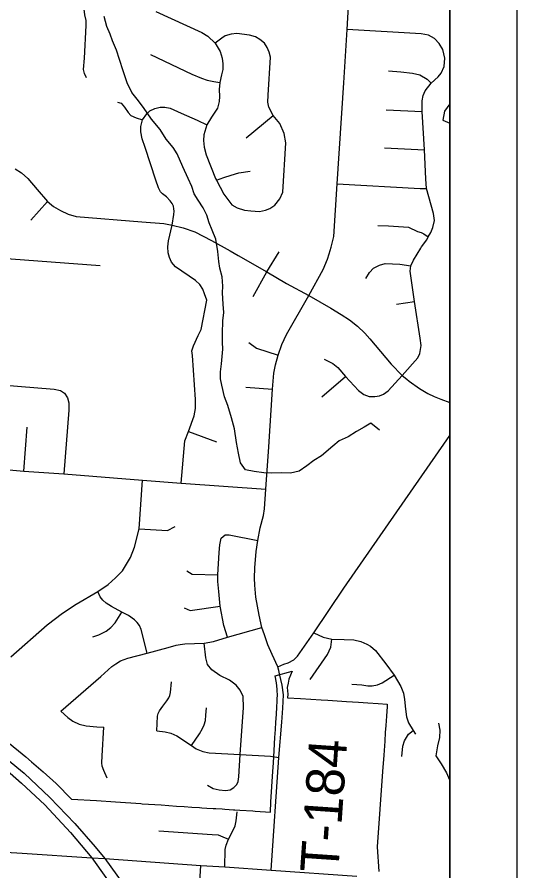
# Model space of a CAD drawing. Extents: x 0 to 34, y 0 to 22.
# Drawn here: x 28.267 to 29.011, y 5.753 to 7.023 of the extents above; entities that cross this region are included whole.
import ezdxf

# ---------------------------------------------------------------- set-up
doc = ezdxf.new("R2010")
doc.units = 0
for name, color, linetype in [('GM_X_City_Street', 7, 'Continuous'), ('GM_X_Corporation', 7, 'Continuous'), ('GM_X_County_Road', 7, 'Continuous'), ('GM_X_Interstate_Route', 7, 'Continuous'), ('GM_X_Minor_River', 7, 'Continuous'), ('GM_X_Township_Road', 7, 'Continuous'), ('GM_X_Township_Road_Text', 7, 'Continuous'), ('SH_Data', 7, 'Continuous')]:
    doc.layers.add(name, color=color, linetype=linetype)

msp = doc.modelspace()

# ---------------------------------------------------------------- linework, layer by layer
at = {"layer": 'GM_X_City_Street'}
for p, q in [((28.6081, 6.8439), (28.6479, 6.8769)), ((28.8166, 6.8855), (28.8699, 6.8828)), ((28.8141, 6.8288), (28.8733, 6.8258)), ((28.2873, 6.7211), (28.312, 6.7488)), ((28.6387, 6.6443), (28.6569, 6.6739)), ((28.6182, 6.6075), (28.6387, 6.6443)), ((28.8318, 6.5961), (28.8588, 6.6001)), ((28.7205, 6.4584), (28.7556, 6.4884)), ((28.84, 6.4902), (28.8471, 6.4846)), ((28.6074, 6.4726), (28.6472, 6.4697)), ((28.277, 6.3475), (28.2821, 6.4134)), ((28.5219, 6.4067), (28.5638, 6.3911))]:
    msp.add_line(p, q, dxfattribs=at)
for points in [[(28.3703, 6.933), (28.3674, 6.9396), (28.3655, 6.9453), (28.367, 6.9622), (28.3698, 7.0108), (28.3698, 7.0185), (28.3677, 7.027), (28.3665, 7.0352), (28.3679, 7.0488)], [(28.4733, 7.0319), (28.5417, 7.0004), (28.5508, 6.9952), (28.5617, 6.9846), (28.5692, 6.9721), (28.5723, 6.9622), (28.5734, 6.9537), (28.5734, 6.9456), (28.5714, 6.9375), (28.5685, 6.9263), (28.5679, 6.9159), (28.5681, 6.9052), (28.5679, 6.8977), (28.5654, 6.888), (28.5564, 6.8744), (28.5494, 6.863), (28.545, 6.8483), (28.5442, 6.84), (28.5452, 6.8297), (28.5483, 6.8185), (28.5623, 6.783), (28.5636, 6.7806), (28.5745, 6.7601), (28.5868, 6.744), (28.5947, 6.7394), (28.6053, 6.7359), (28.615, 6.735), (28.6277, 6.7342), (28.6366, 6.7359), (28.6432, 6.7386), (28.6508, 6.7437)], [(28.6373, 6.3207), (28.6417, 6.3841), (28.6472, 6.4697), (28.6491, 6.4936), (28.6514, 6.5057), (28.6557, 6.5205), (28.6611, 6.5362), (28.668, 6.551), (28.7011, 6.6092), (28.7224, 6.6478), (28.7291, 6.6631), (28.7315, 6.6709), (28.7345, 6.6811), (28.7386, 6.6971), (28.7436, 6.7755), (28.7532, 6.9254), (28.7582, 7.0052), (28.7603, 7.0396)], [(28.879, 6.6963), (28.8829, 6.7031), (28.886, 6.7103), (28.8884, 6.7205), (28.8866, 6.7311), (28.8763, 6.7682), (28.8753, 6.7828), (28.8733, 6.8258), (28.8699, 6.8828), (28.8699, 6.8987), (28.8717, 6.9069), (28.8744, 6.9136), (28.8836, 6.9249), (28.8936, 6.9343), (28.8984, 6.94), (28.9027, 6.95), (28.9038, 6.9623), (28.9006, 6.9751), (28.8954, 6.9842), (28.8883, 6.9917), (28.8795, 6.9963), (28.8683, 6.9983), (28.7582, 7.0052)], [(28.6508, 6.7437), (28.6582, 6.7529), (28.6623, 6.7627), (28.6668, 6.8365), (28.6643, 6.8502), (28.6582, 6.8652), (28.6479, 6.8769), (28.6419, 6.8894), (28.6404, 6.8969), (28.6406, 6.9074), (28.644, 6.964), (28.6423, 6.9713), (28.6394, 6.9783), (28.6353, 6.9847), (28.6285, 6.9903), (28.6217, 6.9939), (28.6131, 6.9967), (28.5942, 6.9989), (28.5854, 6.9982), (28.5769, 6.9956), (28.5716, 6.9923), (28.5617, 6.9846)], [(28.4653, 6.968), (28.5272, 6.9386), (28.5413, 6.9324), (28.5497, 6.9296), (28.5598, 6.9276), (28.5685, 6.9263)], [(28.8197, 6.9434), (28.838, 6.9418), (28.8555, 6.9402), (28.8665, 6.9377), (28.8774, 6.9311), (28.8836, 6.9249)], [(28.4166, 6.8966), (28.4216, 6.8953), (28.4267, 6.8894), (28.4322, 6.8815), (28.4364, 6.8769), (28.4441, 6.8734), (28.4535, 6.8703)], [(28.4977, 6.7137), (28.5002, 6.7295), (28.5009, 6.7348), (28.5003, 6.7383), (28.4998, 6.7421), (28.4978, 6.746), (28.4947, 6.75), (28.4891, 6.7559), (28.4836, 6.7605), (28.4805, 6.7632), (28.4774, 6.7691), (28.4735, 6.7809), (28.4574, 6.8294), (28.4533, 6.8424), (28.4511, 6.8529), (28.4511, 6.8606), (28.4535, 6.8703), (28.4599, 6.8797), (28.4647, 6.8839), (28.4721, 6.8876), (28.48, 6.8894), (28.4869, 6.8894), (28.495, 6.8878), (28.511, 6.8806), (28.5352, 6.8701), (28.5494, 6.863)], [(28.264, 6.7976), (28.2735, 6.7917), (28.283, 6.7832), (28.2966, 6.7669), (28.312, 6.7488), (28.3211, 6.7416), (28.3315, 6.7354), (28.3431, 6.7301), (28.3549, 6.7266), (28.4524, 6.7187), (28.4854, 6.7164), (28.4977, 6.7137), (28.5142, 6.7098), (28.5317, 6.7037), (28.5565, 6.691), (28.584, 6.6754), (28.596, 6.6686)], [(28.5636, 6.7806), (28.5748, 6.7848), (28.5858, 6.7884), (28.5972, 6.7917), (28.6139, 6.7941)], [(28.7436, 6.7755), (28.8671, 6.7684), (28.8763, 6.7682)], [(28.5114, 6.3296), (28.5166, 6.3929), (28.5219, 6.4067), (28.5304, 6.4302), (28.5326, 6.4409), (28.5327, 6.4542), (28.5278, 6.5196), (28.5271, 6.5267), (28.5294, 6.5344), (28.5367, 6.5494), (28.5408, 6.5585), (28.5493, 6.6021), (28.5461, 6.6115), (28.5433, 6.6187), (28.5387, 6.6255), (28.5323, 6.6314), (28.5025, 6.6517), (28.497, 6.6589), (28.4937, 6.6656), (28.4918, 6.6728), (28.4915, 6.6813), (28.4924, 6.6904), (28.4977, 6.7137)], [(28.804, 6.7132), (28.8197, 6.7126), (28.8496, 6.711), (28.8632, 6.7045), (28.8685, 6.7029), (28.8726, 6.701), (28.879, 6.6963)], [(28.84, 6.4902), (28.8635, 6.5164), (28.8664, 6.5227), (28.8683, 6.5348), (28.8669, 6.5457), (28.8588, 6.6001), (28.8523, 6.6453), (28.8532, 6.6531), (28.8569, 6.6617), (28.868, 6.6795), (28.869, 6.6813), (28.8767, 6.6918), (28.879, 6.6963)], [(28.0413, 6.6621), (28.0579, 6.6738), (28.0641, 6.6777), (28.0729, 6.6787), (28.0821, 6.6775), (28.1973, 6.6683), (28.2245, 6.6664), (28.3905, 6.654)], [(28.596, 6.6686), (28.6387, 6.6443), (28.6681, 6.627), (28.7011, 6.6092)], [(28.7859, 6.6346), (28.7914, 6.6435), (28.7977, 6.65), (28.8064, 6.6542), (28.815, 6.6565), (28.8366, 6.6556), (28.8532, 6.6531)], [(28.7011, 6.6092), (28.7341, 6.5902), (28.7495, 6.5809), (28.762, 6.5728), (28.7736, 6.5635), (28.7844, 6.5531), (28.7922, 6.5447), (28.8001, 6.5354), (28.8239, 6.5069), (28.84, 6.4902)], [(28.6117, 6.5394), (28.6235, 6.5307), (28.6557, 6.5205)], [(28.7241, 6.5143), (28.7311, 6.5109), (28.7371, 6.5079), (28.7445, 6.502), (28.7556, 6.4884), (28.7751, 6.4677), (28.7833, 6.4618), (28.7912, 6.4589), (28.7994, 6.4586), (28.8062, 6.4599), (28.8123, 6.4622), (28.8195, 6.4673), (28.84, 6.4902)], [(27.6255, 6.5037), (27.6337, 6.5034), (27.6821, 6.4998), (27.7013, 6.4965), (27.7199, 6.4915), (27.7363, 6.4855), (27.7527, 6.4784), (27.7781, 6.4619), (27.8264, 6.4218), (27.8411, 6.4075), (27.8603, 6.3952), (27.8815, 6.3851), (27.8967, 6.3804), (27.9175, 6.3761), (27.9561, 6.3728), (28.2171, 6.3532), (28.277, 6.3475), (28.3364, 6.3435), (28.4536, 6.3344), (28.5114, 6.3296), (28.6373, 6.3207)], [(27.8589, 6.5058), (28.1571, 6.4839), (28.2185, 6.4783), (28.3223, 6.4699), (28.3315, 6.4676), (28.3375, 6.4636), (28.3418, 6.457), (28.3441, 6.4492), (28.3439, 6.4383), (28.3364, 6.3435)], [(28.8471, 6.4846), (28.8506, 6.4817), (28.866, 6.4705), (28.8783, 6.4635), (28.8876, 6.4586), (28.898, 6.4546), (28.9111, 6.4499)], [(28.6551, 6.0565), (28.664, 6.0604), (28.6706, 6.0626), (28.679, 6.0668), (28.6846, 6.0723), (28.7088, 6.1069), (28.7535, 6.1733), (28.9068, 6.3944), (28.9111, 6.4009)], [(28.2574, 6.0715), (28.3117, 6.1191), (28.3344, 6.1363), (28.355, 6.1499), (28.387, 6.1685), (28.4025, 6.1788), (28.4136, 6.1887), (28.4236, 6.1994), (28.4356, 6.219), (28.4416, 6.2344), (28.4488, 6.2619), (28.4536, 6.3344)], [(28.6551, 6.0565), (28.6465, 6.0749), (28.6403, 6.0894), (28.6352, 6.1042), (28.6313, 6.1152), (28.6271, 6.1332), (28.6223, 6.1602), (28.6207, 6.1782), (28.6205, 6.1885), (28.6207, 6.2038), (28.623, 6.2282), (28.6251, 6.2446), (28.629, 6.2635), (28.6338, 6.2817), (28.6354, 6.2914), (28.6373, 6.3207)], [(28.4488, 6.2619), (28.4909, 6.2596), (28.502, 6.2655)], [(28.5801, 6.1007), (28.5748, 6.1182), (28.569, 6.1466), (28.567, 6.1687), (28.5656, 6.1835), (28.5656, 6.1934), (28.5679, 6.2264), (28.5688, 6.2381), (28.5707, 6.2478), (28.5767, 6.2529), (28.5827, 6.2531), (28.6251, 6.2446)], [(28.5195, 6.1991), (28.5273, 6.1945), (28.5656, 6.1934)], [(28.4605, 6.0768), (28.4514, 6.112), (28.449, 6.1179), (28.4458, 6.1224), (28.4418, 6.1266), (28.4325, 6.133), (28.4227, 6.1379), (28.4073, 6.1461), (28.3993, 6.1512), (28.3945, 6.1557), (28.3908, 6.1604), (28.387, 6.1685)], [(28.3797, 6.1012), (28.3884, 6.1039), (28.3993, 6.1094), (28.4062, 6.1151), (28.4128, 6.122), (28.4227, 6.1379)], [(28.5156, 6.1443), (28.5246, 6.1404), (28.569, 6.1466)], [(28.4139, 6.061), (28.4206, 6.0656), (28.4318, 6.0695), (28.4605, 6.0768), (28.4917, 6.0854), (28.5038, 6.0885), (28.5099, 6.0898), (28.5166, 6.0906), (28.5453, 6.0917), (28.5594, 6.0943), (28.5801, 6.1007), (28.6313, 6.1152)], [(28.7088, 6.1069), (28.7228, 6.1007), (28.7353, 6.0977), (28.754, 6.097), (28.768, 6.0966), (28.7786, 6.094), (28.7876, 6.0903), (28.7931, 6.0871), (28.8007, 6.0809), (28.8161, 6.0608), (28.8281, 6.0439), (28.838, 6.0273), (28.8421, 6.0174), (28.8436, 6.008), (28.845, 5.9934), (28.8468, 5.9821), (28.8497, 5.9733), (28.8564, 5.9619), (28.8599, 5.9564)], [(28.5992, 5.9262), (28.6039, 5.9958), (28.6036, 6.0122), (28.5992, 6.0216), (28.593, 6.0292), (28.5833, 6.0366), (28.5686, 6.0438), (28.5568, 6.0518), (28.5504, 6.0597), (28.5481, 6.07), (28.5453, 6.0917)], [(28.7032, 6.0375), (28.7291, 6.0747), (28.7339, 6.0857), (28.7353, 6.0977)], [(28.3318, 5.9904), (28.3915, 6.0423), (28.4079, 6.0571), (28.4139, 6.061)], [(28.7652, 6.0308), (28.78, 6.0299), (28.7893, 6.0284), (28.7957, 6.0284), (28.8036, 6.0299), (28.8103, 6.0328), (28.8281, 6.0439)], [(28.4747, 5.961), (28.4761, 5.983), (28.4768, 5.9868), (28.479, 5.9911), (28.4838, 5.9979), (28.4897, 6.0059), (28.4926, 6.0103), (28.4944, 6.0139), (28.4953, 6.0183), (28.497, 6.0342)], [(28.3318, 5.9904), (28.3423, 5.9811), (28.3499, 5.9754), (28.3595, 5.9711), (28.3696, 5.9686), (28.3858, 5.9674), (28.396, 5.9665)], [(28.5263, 5.9396), (28.5384, 5.9569), (28.5431, 5.9646), (28.5454, 5.9701), (28.5472, 5.9764), (28.5481, 5.9843), (28.5487, 5.9955)], [(28.4008, 5.8908), (28.3958, 5.9022), (28.3936, 5.9085), (28.3928, 5.9137), (28.3934, 5.9241), (28.396, 5.9665)], [(28.4747, 5.961), (28.4872, 5.9597), (28.4956, 5.9578), (28.5049, 5.9539), (28.5263, 5.9396), (28.5337, 5.9342), (28.5432, 5.9303), (28.5529, 5.9286), (28.5992, 5.9262), (28.6443, 5.9234), (28.6567, 5.9215)], [(28.8398, 5.9231), (28.8412, 5.9383), (28.8436, 5.9465), (28.8465, 5.9514), (28.8497, 5.9561), (28.8564, 5.9619)], [(28.5504, 5.8804), (28.5588, 5.8755), (28.5679, 5.8732), (28.5773, 5.8723), (28.5842, 5.8733), (28.5897, 5.8768), (28.5939, 5.8813), (28.5961, 5.886), (28.5971, 5.893), (28.5992, 5.9262)]]:
    msp.add_lwpolyline(points, dxfattribs=at)
at = {"layer": 'GM_X_Corporation'}
for points in [[(28.9111, 5.5325), (28.9111, 9.2728)], [(28.9111, 3.3841), (28.9111, 8.322)], [(28.9111, 3.3841), (28.9111, 8.322)], [(28.2529, 5.9443), (28.2691, 5.9315), (28.28, 5.9227), (28.2884, 5.9153), (28.3056, 5.9001), (28.3248, 5.8827), (28.3481, 5.8597), (28.3852, 5.8573), (28.4134, 5.8554), (28.4511, 5.8529), (28.453, 5.8528), (28.4813, 5.8509), (28.493, 5.8501), (28.5043, 5.8493), (28.5157, 5.8486), (28.5271, 5.8478), (28.5384, 5.8471), (28.5419, 5.8468), (28.5496, 5.8463), (28.5588, 5.8457), (28.5629, 5.8455), (28.572, 5.8449), (28.5761, 5.8446), (28.5893, 5.8437), (28.591, 5.8436), (28.5987, 5.8431), (28.6177, 5.842), (28.6212, 5.8417), (28.644, 5.8404), (28.6449, 5.8555), (28.6458, 5.8704), (28.6467, 5.8856), (28.6476, 5.9009), (28.6484, 5.9137), (28.6494, 5.9318), (28.6507, 5.9513), (28.6515, 5.9631), (28.6522, 5.9743), (28.6529, 5.9857), (28.6536, 5.9971), (28.6541, 6.0048), (28.6543, 6.0087), (28.6546, 6.0141), (28.6543, 6.0213), (28.6542, 6.0234), (28.6531, 6.0326), (28.651, 6.0433), (28.6763, 6.0502), (28.6717, 6.0383), (28.6703, 6.032), (28.6691, 6.0258), (28.6696, 6.0207), (28.6699, 6.0156), (28.6696, 6.0104), (28.6889, 6.0092), (28.7194, 6.0073), (28.7297, 6.0067), (28.7575, 6.0049), (28.775, 6.0038), (28.789, 6.0028), (28.8047, 6.0017), (28.8181, 6.0009), (28.8179, 5.9976), (28.8168, 5.9829), (28.8159, 5.9691), (28.8151, 5.9589), (28.8142, 5.9457), (28.8127, 5.925), (28.8109, 5.9006), (28.8028, 5.7885), (28.8055, 5.7519)]]:
    msp.add_lwpolyline(points, dxfattribs=at)
at = {"layer": 'GM_X_County_Road'}
for points in [[(27.6019, 5.8287), (27.6146, 5.8283), (27.6326, 5.8262), (27.6506, 5.8224), (27.6602, 5.8205), (27.7773, 5.8125), (27.9304, 5.8016), (28.0938, 5.7917), (28.1487, 5.7871), (28.2253, 5.7823), (28.2745, 5.7791)], [(28.2745, 5.7791), (28.378, 5.7724), (28.3973, 5.771), (28.5406, 5.7609), (28.5495, 5.7603)], [(28.5495, 5.7603), (28.576, 5.7586), (28.6454, 5.7539), (28.7727, 5.7451)]]:
    msp.add_lwpolyline(points, dxfattribs=at)
at = {"layer": 'GM_X_Interstate_Route'}
for points in [[(27.4056, 6.2232), (27.6132, 6.1686), (27.6223, 6.1662), (27.8417, 6.1095), (27.9277, 6.086), (27.9825, 6.0694), (28.0281, 6.0509), (28.065, 6.0345), (28.1073, 6.0139), (28.1462, 5.9926), (28.1929, 5.9636), (28.2273, 5.939), (28.2773, 5.898), (28.3155, 5.8621), (28.353, 5.8235), (28.3833, 5.7884), (28.3973, 5.771), (28.4245, 5.7342)], [(28.2272, 5.9224), (28.235, 5.9164), (28.2736, 5.8833), (28.308, 5.851), (28.3462, 5.8098), (28.378, 5.7724), (28.4356, 5.6912), (28.4633, 5.6449), (28.4952, 5.5818), (28.5056, 5.5585), (28.5181, 5.5286), (28.5278, 5.5014), (28.5396, 5.4644), (28.549, 5.4299), (28.5567, 5.3977), (28.5611, 5.3773), (28.5657, 5.3503), (28.5694, 5.3196), (28.5734, 5.2922), (28.5751, 5.2643)]]:
    msp.add_lwpolyline(points, dxfattribs=at)
at = {"layer": 'GM_X_Minor_River'}
for points in [[(28.8062, 6.4089), (28.7934, 6.4189), (28.7835, 6.4133), (28.7724, 6.4066), (28.7598, 6.3987), (28.7464, 6.3928), (28.7369, 6.3849), (28.72, 6.3707), (28.7086, 6.3636), (28.6983, 6.3557), (28.6868, 6.3479), (28.6739, 6.3446), (28.6602, 6.3451), (28.6462, 6.3448), (28.634, 6.3453), (28.6196, 6.347), (28.6068, 6.3498), (28.5993, 6.3601), (28.5967, 6.3746), (28.5935, 6.3905), (28.5906, 6.4107), (28.5859, 6.427), (28.5804, 6.4453), (28.5759, 6.4583), (28.5715, 6.4758), (28.5697, 6.4853), (28.5695, 6.4955), (28.5711, 6.5073), (28.5723, 6.5183), (28.5732, 6.5293), (28.5729, 6.5399), (28.5727, 6.5524), (28.5732, 6.5714), (28.5745, 6.5839), (28.5739, 6.5964), (28.5729, 6.6132), (28.573, 6.623), (28.572, 6.6371), (28.5687, 6.6496), (28.5673, 6.6595), (28.5659, 6.6747), (28.5626, 6.693), (28.5575, 6.7063), (28.553, 6.7173), (28.5493, 6.7288), (28.5437, 6.7395), (28.5363, 6.7509), (28.5303, 6.7605), (28.527, 6.7715), (28.5218, 6.7833), (28.5136, 6.8005), (28.5051, 6.8199), (28.4991, 6.8295), (28.4889, 6.8417), (28.48, 6.8562), (28.4672, 6.8715), (28.4553, 6.8887), (28.4455, 6.9014), (28.4376, 6.9113), (28.4306, 6.9258), (28.425, 6.9437), (28.4195, 6.9605), (28.4147, 6.9742), (28.4088, 6.9883), (28.4055, 6.9978), (28.4006, 7.0092), (28.3966, 7.0244)], [(28.9111, 6.8943), (28.9034, 6.8835), (28.9006, 6.8699), (28.9111, 6.8654)], [(28.8942, 5.9727), (28.8963, 5.962), (28.8959, 5.9514), (28.8927, 5.9389), (28.8903, 5.9241), (28.8981, 5.9119), (28.906, 5.8989), (28.9108, 5.8883), (28.9111, 5.8876)]]:
    msp.add_lwpolyline(points, dxfattribs=at)
at = {"layer": 'GM_X_Township_Road'}
for points in [[(28.6576, 6.0462), (28.6564, 6.0511), (28.6551, 6.0565)], [(28.6454, 5.7539), (28.6567, 5.9215), (28.6608, 5.9741), (28.6624, 5.9949), (28.6636, 6.0149), (28.6616, 6.0294), (28.6576, 6.0462)], [(28.576, 5.7586), (28.5768, 5.7846), (28.5783, 5.7913), (28.5817, 5.7999), (28.5895, 5.8153), (28.5915, 5.8199), (28.5932, 5.8275), (28.5947, 5.8408)], [(28.4777, 5.8124), (28.5575, 5.8069), (28.5661, 5.8062), (28.5731, 5.8036), (28.5817, 5.7999)], [(28.5525, 5.6244), (28.5431, 5.6302), (28.5367, 5.636), (28.5334, 5.6414), (28.5312, 5.649), (28.5344, 5.6608), (28.538, 5.7196), (28.5406, 5.7609)]]:
    msp.add_lwpolyline(points, dxfattribs=at)
at = {"layer": 'SH_Data'}
for p, q in [((29.0111, 10.2841), (29.0111, 3.2841)), ((28.9111, 10.1841), (28.9111, 3.3841))]:
    msp.add_line(p, q, dxfattribs=at)

# ---------------------------------------------------------------- texts
at = {"layer": 'GM_X_Township_Road_Text'}
msp.add_text('T-184', height=0.05682, rotation=86.0741, dxfattribs=at).set_placement((28.7449, 5.7488))

doc.saveas('drawing.dxf')
